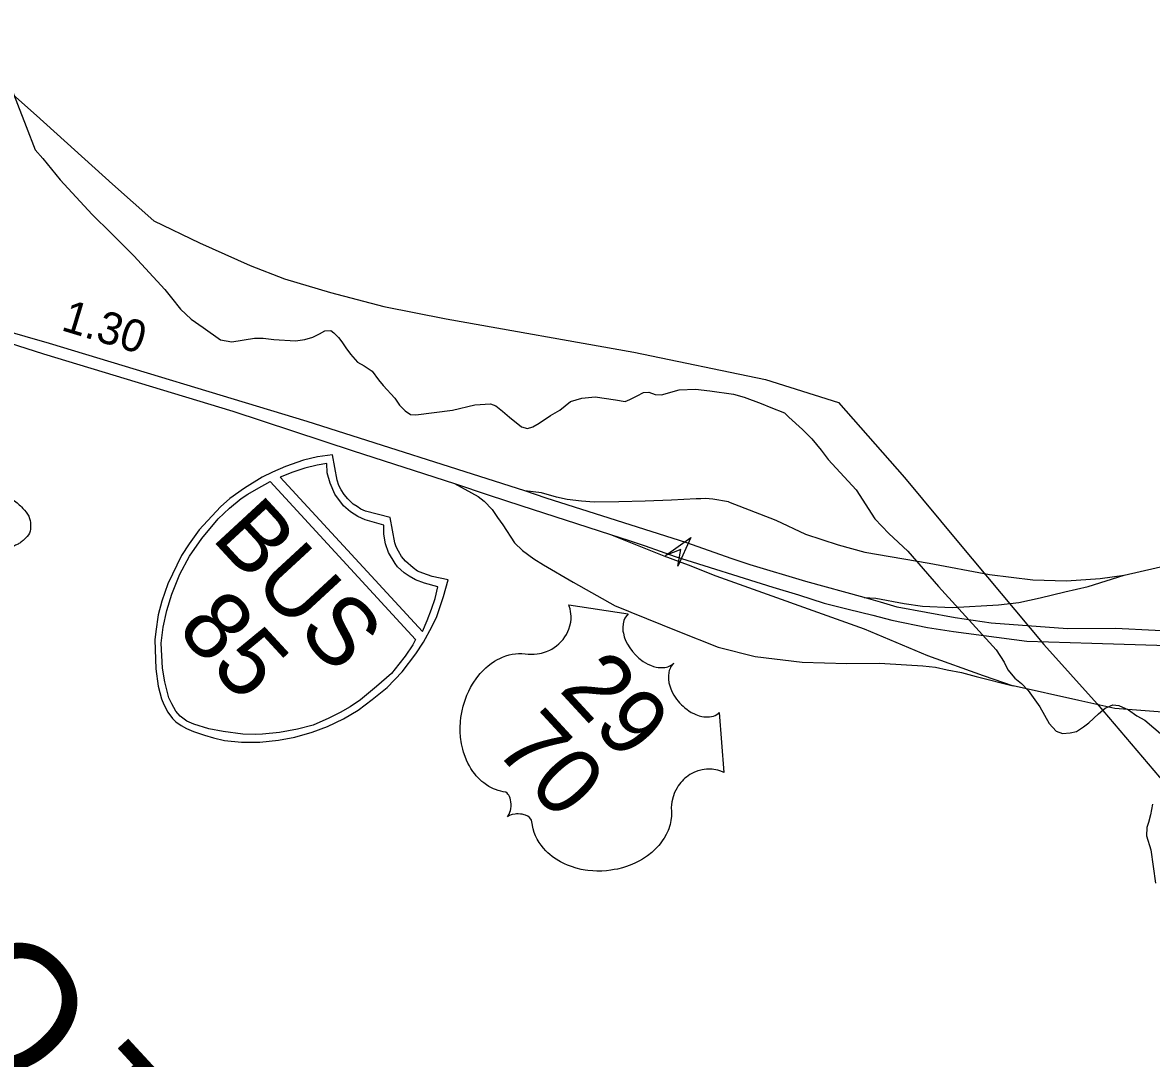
# Model space of a CAD drawing. Extents: x 1695041 to 1706254, y 786537 to 798223.
# Drawn here: x 1703431.2 to 1703634.1, y 796781.2 to 796967.3 of the extents above; entities that cross this region are included whole.
import ezdxf

# ---------------------------------------------------------------- set-up
doc = ezdxf.new("R2010")
doc.units = 0
for name, color, linetype in [('Default', 7, 'Continuous'), ('Old_Level_2', 7, 'Continuous'), ('Old_Level_27', 7, 'Continuous'), ('Old_Level_30', 7, 'Continuous'), ('Old_Level_47', 7, 'Continuous')]:
    doc.layers.add(name, color=color, linetype=linetype)

msp = doc.modelspace()

# ---------------------------------------------------------------- linework, layer by layer
at = {"layer": 'Default'}
msp.add_lwpolyline([(1703414.85, 796967.32), (1703433.69, 796950.61), (1703447.36, 796938.29), (1703454.79, 796931.67), (1703463.03, 796927.76), (1703472.14, 796923.67), (1703478.29, 796921.24), (1703486.59, 796918.81), (1703496.14, 796916.29), (1703507.34, 796914.06), (1703541.09, 796908.09), (1703564.75, 796903.15), (1703577.89, 796899.03), (1703589.73, 796885.57), (1703599.49, 796873.87), (1703614.79, 796855.58), (1703624.36, 796844.92), (1703635.61, 796831.69), (1703649.41, 796815.64), (1703662.09, 796801.81), (1703669.34, 796799.45)], dxfattribs=at)
for points in [[(1703458.16, 796842.23), (1703458.78, 796841.67), (1703459.69, 796841), (1703460.68, 796840.45), (1703461.92, 796839.91), (1703463.9, 796839.26), (1703465.52, 796838.77), (1703467.5, 796838.29), (1703470.57, 796838.02), (1703473.87, 796837.98), (1703477.23, 796838.34), (1703480.17, 796838.89), (1703483.25, 796839.82), (1703486.03, 796840.79), (1703488.93, 796842.19), (1703491.54, 796843.77), (1703494.05, 796845.66), (1703496.73, 796847.85), (1703499.43, 796850.66), (1703501.89, 796853.86), (1703503.28, 796856), (1703504.81, 796858.72), (1703505.66, 796860.58), (1703506.9, 796864.2), (1703507.69, 796867.15), (1703504.84, 796867.77), (1703503.18, 796868.35), (1703502.23, 796868.75), (1703501.43, 796869.34), (1703500.05, 796870.51), (1703499.33, 796871.37), (1703498.79, 796872.3), (1703498.34, 796873.08), (1703498.11, 796873.85), (1703497.32, 796878.38), (1703492.86, 796879.53), (1703492.04, 796879.87), (1703491.35, 796880.36), (1703490.64, 796880.8), (1703489.7, 796881.73), (1703489.04, 796882.49), (1703488.47, 796883.38), (1703488.04, 796884.1), (1703487.74, 796885.07), (1703486.91, 796889.66), (1703484.21, 796889.28), (1703481.72, 796888.7), (1703478.5, 796887.56), (1703476.15, 796886.52), (1703474.28, 796885.6), (1703471.09, 796883.65), (1703468.49, 796881.77), (1703466.79, 796880.28), (1703462.93, 796876.16), (1703461.14, 796873.67), (1703459.78, 796871.56), (1703457.35, 796866.47), (1703456.25, 796863.33), (1703455.61, 796860.91), (1703455.15, 796857.91), (1703455.01, 796856.39), (1703455.15, 796851.2), (1703455.61, 796848.07), (1703456.2, 796845.77), (1703456.59, 796844.79), (1703457.32, 796843.37)], [(1703485.89, 796888.09), (1703484.16, 796887.79), (1703481.94, 796887.25), (1703479.82, 796886.5), (1703477.53, 796885.62), (1703503.08, 796857.91), (1703503.93, 796859.88), (1703504.74, 796861.91), (1703505.39, 796863.85), (1703505.86, 796865.91), (1703503.44, 796866.56), (1703501.86, 796867.19), (1703500.71, 796867.82), (1703499.83, 796868.43), (1703498.63, 796869.53), (1703498.17, 796870.09), (1703497.01, 796872.11), (1703496.43, 796873.66), (1703496.16, 796875.39), (1703496.17, 796877.01), (1703492.82, 796877.98), (1703491.49, 796878.56), (1703490.17, 796879.41), (1703488.89, 796880.5), (1703487.35, 796882.58), (1703486.49, 796884.53), (1703485.98, 796886.42)], [(1703501.87, 796856.48), (1703501.36, 796855.47), (1703500, 796853.45), (1703498.86, 796852.01), (1703497.53, 796850.36), (1703494.81, 796848), (1703491.96, 796845.61), (1703490.11, 796844.37), (1703488.33, 796843.34), (1703486.27, 796842.29), (1703483.42, 796841.03), (1703480.64, 796840.35), (1703477.42, 796839.74), (1703474.36, 796839.47), (1703473.06, 796839.39), (1703470.81, 796839.42), (1703467.24, 796839.95), (1703464.72, 796840.42), (1703461.99, 796841.24), (1703460.73, 796841.78), (1703459.52, 796842.65), (1703458.77, 796843.58), (1703458.07, 796844.91), (1703457.51, 796845.99), (1703456.78, 796848.82), (1703456.39, 796851.3), (1703456.13, 796855.78), (1703456.47, 796858.65), (1703457.17, 796861.68), (1703458.04, 796864.61), (1703459.46, 796868.18), (1703461.22, 796871.41), (1703463.41, 796874.59), (1703466.39, 796878.13), (1703468.41, 796880.08), (1703470.5, 796881.78), (1703471.72, 796882.55), (1703473.24, 796883.49), (1703475.69, 796884.82)], [(1703546.78, 796871.52), (1703551.36, 796874.79), (1703549.03, 796869.66), (1703549.57, 796872.62)], [(1703540.06, 796861.05), (1703539.82, 796860.79), (1703539.57, 796860.45), (1703539.46, 796860.26), (1703539.29, 796859.84), (1703539.15, 796859.27), (1703539.11, 796858.63), (1703539.14, 796857.98), (1703539.21, 796857.58), (1703539.38, 796856.94), (1703539.62, 796856.28), (1703539.96, 796855.6), (1703540.35, 796854.95), (1703540.84, 796854.3), (1703541.37, 796853.7), (1703542.01, 796853.1), (1703542.79, 796852.53), (1703543.18, 796852.28), (1703543.63, 796852.03), (1703544.08, 796851.82), (1703544.62, 796851.63), (1703545.09, 796851.51), (1703545.47, 796851.44), (1703546.09, 796851.4), (1703546.66, 796851.44), (1703546.94, 796851.5), (1703547.21, 796851.56), (1703547.7, 796851.78), (1703547.9, 796851.89), (1703548.27, 796852.18), (1703548, 796851.9), (1703547.85, 796851.7), (1703547.71, 796851.49), (1703547.6, 796851.25), (1703547.45, 796850.87), (1703547.37, 796850.52), (1703547.3, 796849.94), (1703547.3, 796849.62), (1703547.31, 796849.35), (1703547.41, 796848.66), (1703547.62, 796847.94), (1703547.73, 796847.6), (1703547.88, 796847.27), (1703548.07, 796846.86), (1703548.3, 796846.47), (1703548.54, 796846.09), (1703548.79, 796845.72), (1703549.08, 796845.36), (1703549.33, 796845.08), (1703549.64, 796844.74), (1703549.95, 796844.45), (1703550.28, 796844.17), (1703550.66, 796843.87), (1703550.98, 796843.64), (1703551.43, 796843.36), (1703551.86, 796843.14), (1703552.26, 796842.96), (1703552.82, 796842.76), (1703553.3, 796842.63), (1703553.69, 796842.57), (1703554.19, 796842.53), (1703554.72, 796842.55), (1703555.08, 796842.59), (1703555.4, 796842.69), (1703555.73, 796842.81), (1703556.03, 796842.98), (1703556.27, 796843.15), (1703556.46, 796843.32), (1703557.25, 796832.56), (1703557.06, 796832.65), (1703556.58, 796832.83), (1703556.18, 796832.96), (1703555.48, 796833.11), (1703555.15, 796833.14), (1703554.81, 796833.16), (1703554.47, 796833.16), (1703554.16, 796833.15), (1703553.75, 796833.1), (1703553.35, 796833.03), (1703552.93, 796832.93), (1703552.58, 796832.83), (1703551.91, 796832.56), (1703551.51, 796832.36), (1703551.19, 796832.17), (1703550.57, 796831.74), (1703550.29, 796831.51), (1703550.03, 796831.27), (1703549.76, 796831), (1703549.52, 796830.73), (1703549.29, 796830.43), (1703549.09, 796830.16), (1703548.87, 796829.81), (1703548.62, 796829.39), (1703548.42, 796828.94), (1703548.14, 796828.16), (1703547.93, 796827.29), (1703547.86, 796826.75), (1703547.83, 796826.25), (1703547.86, 796825.56), (1703547.87, 796825.19), (1703547.85, 796824.73), (1703547.76, 796823.93), (1703547.69, 796823.57), (1703547.6, 796823.19), (1703547.49, 796822.82), (1703547.36, 796822.43), (1703547.24, 796822.1), (1703546.91, 796821.39), (1703546.54, 796820.76), (1703546.33, 796820.43), (1703545.83, 796819.76), (1703545.57, 796819.43), (1703545.02, 796818.84), (1703544.31, 796818.17), (1703543.57, 796817.6), (1703542.66, 796816.99), (1703542.09, 796816.66), (1703541.38, 796816.31), (1703540.76, 796816.03), (1703539.79, 796815.66), (1703539.04, 796815.44), (1703538.14, 796815.21), (1703537.57, 796815.1), (1703536.94, 796815), (1703536.2, 796814.91), (1703535.37, 796814.85), (1703534.44, 796814.85), (1703533.73, 796814.87), (1703532.85, 796814.96), (1703532.34, 796815.03), (1703531.64, 796815.15), (1703530.73, 796815.37), (1703529.89, 796815.64), (1703529.2, 796815.89), (1703528.62, 796816.15), (1703527.91, 796816.5), (1703526.81, 796817.18), (1703526.43, 796817.45), (1703526.01, 796817.79), (1703525.63, 796818.13), (1703525.28, 796818.47), (1703524.83, 796818.95), (1703524.42, 796819.47), (1703524.07, 796819.98), (1703523.73, 796820.55), (1703523.42, 796821.18), (1703523.19, 796821.79), (1703522.99, 796822.45), (1703522.77, 796823.66), (1703522.68, 796823.99), (1703522.6, 796824.15), (1703522.34, 796824.46), (1703522.02, 796824.68), (1703521.64, 796824.86), (1703521.39, 796824.95), (1703521.03, 796825.04), (1703520.73, 796825.09), (1703520.33, 796825.11), (1703520.03, 796825.1), (1703519.79, 796825.09), (1703519.25, 796824.99), (1703519.02, 796824.92), (1703518.74, 796824.81), (1703518.37, 796824.6), (1703518.66, 796825.05), (1703518.82, 796825.4), (1703518.91, 796825.74), (1703518.98, 796826.05), (1703519.03, 796826.5), (1703519.04, 796826.87), (1703519.01, 796827.28), (1703518.93, 796827.67), (1703518.85, 796827.96), (1703518.75, 796828.21), (1703518.6, 796828.48), (1703518.45, 796828.68), (1703518.3, 796828.82), (1703518.07, 796828.99), (1703517.61, 796829.08), (1703517.18, 796829.18), (1703516.73, 796829.3), (1703516.23, 796829.48), (1703515.88, 796829.62), (1703515.48, 796829.81), (1703515.04, 796830.06), (1703514.59, 796830.35), (1703514.15, 796830.67), (1703513.78, 796830.96), (1703513.41, 796831.3), (1703513.09, 796831.62), (1703512.77, 796831.97), (1703512.49, 796832.32), (1703512.18, 796832.73), (1703511.82, 796833.26), (1703511.55, 796833.73), (1703511.28, 796834.25), (1703511.02, 796834.79), (1703510.78, 796835.4), (1703510.5, 796836.19), (1703510.34, 796836.77), (1703510.13, 796837.71), (1703509.96, 796838.9), (1703509.9, 796839.86), (1703509.89, 796840.59), (1703509.95, 796841.74), (1703510.02, 796842.45), (1703510.22, 796843.64), (1703510.41, 796844.46), (1703510.57, 796845.03), (1703510.87, 796845.91), (1703511.08, 796846.44), (1703511.41, 796847.18), (1703511.75, 796847.83), (1703512.08, 796848.43), (1703512.31, 796848.79), (1703512.73, 796849.4), (1703513.04, 796849.82), (1703513.49, 796850.36), (1703514.01, 796850.91), (1703514.5, 796851.38), (1703514.93, 796851.75), (1703515.46, 796852.15), (1703516.05, 796852.55), (1703516.59, 796852.86), (1703516.99, 796853.06), (1703517.5, 796853.29), (1703518.09, 796853.51), (1703518.69, 796853.68), (1703519.21, 796853.8), (1703519.8, 796853.89), (1703520.34, 796853.94), (1703520.98, 796853.94), (1703521.59, 796853.9), (1703522.12, 796853.83), (1703522.8, 796853.79), (1703523.19, 796853.8), (1703523.69, 796853.85), (1703524.13, 796853.92), (1703524.51, 796854.01), (1703525.05, 796854.15), (1703525.42, 796854.29), (1703525.97, 796854.53), (1703526.33, 796854.73), (1703526.78, 796855.01), (1703527.18, 796855.29), (1703527.64, 796855.68), (1703527.99, 796856.03), (1703528.38, 796856.47), (1703528.71, 796856.93), (1703528.98, 796857.36), (1703529.25, 796857.89), (1703529.42, 796858.31), (1703529.61, 796858.93), (1703529.74, 796859.54), (1703529.8, 796860.09), (1703529.82, 796860.62), (1703529.78, 796861.08), (1703529.73, 796861.49), (1703529.63, 796861.98), (1703529.5, 796862.43), (1703529.4, 796862.69)]]:
    msp.add_lwpolyline(points, close=True, dxfattribs=at)
msp.add_open_spline([(1703427.95, 796882.37), (1703428.62, 796882.11), (1703429.54, 796881.5), (1703430.47, 796880.88), (1703431.15, 796880.14), (1703432.56, 796878.61), (1703432.63, 796877.07), (1703432.69, 796875.52), (1703431.43, 796874.36), (1703430.87, 796873.83), (1703430.25, 796873.53), (1703429.62, 796873.22), (1703428.92, 796873.09), (1703428.27, 796872.97), (1703427.55, 796872.95), (1703426.83, 796872.93), (1703425.88, 796872.98), (1703424.52, 796873.05), (1703423.16, 796873.21), (1703421.8, 796873.36), (1703420.63, 796873.51)], degree=3, dxfattribs=at)
at = {"layer": 'Old_Level_27'}
for points in [[(1703405.06, 796916.66), (1703416.6, 796913.66), (1703434.95, 796907.77), (1703469.02, 796897.48), (1703490.65, 796890.37), (1703508.83, 796884.48)], [(1703521.5, 796883.15), (1703482.35, 796895.62), (1703436.05, 796909.65), (1703422.42, 796913.54), (1703409.3, 796917.03)], [(1703508.83, 796884.48), (1703515.1, 796882.38), (1703520.76, 796880.56), (1703536.91, 796875.33)], [(1703550.62, 796873.81), (1703525.31, 796881.85), (1703521.5, 796883.15)], [(1703536.91, 796875.33), (1703540.28, 796874.25), (1703543.15, 796873.28), (1703548.53, 796871.37)], [(1703582.51, 796864), (1703572.01, 796866.87), (1703562.02, 796869.86), (1703558.61, 796871), (1703550.62, 796873.81)], [(1703548.53, 796871.37), (1703566.06, 796865.83), (1703570.71, 796864.5), (1703575.31, 796863), (1703579.65, 796861.89), (1703584.08, 796860.85), (1703587.47, 796859.94), (1703593.9, 796858.6), (1703598.58, 796857.87), (1703611.75, 796856.13), (1703623.45, 796855.82), (1703640.92, 796855.28), (1703649.76, 796855.1)], [(1703650.31, 796857.69), (1703641.96, 796857.69), (1703627.68, 796858.45), (1703619.04, 796858.36), (1703605.35, 796859.39), (1703598.85, 796860.35), (1703588.44, 796862.27), (1703585.42, 796863.18), (1703582.51, 796864)]]:
    msp.add_lwpolyline(points, dxfattribs=at)
at = {"layer": 'Old_Level_30'}
for points in [[(1703428.73, 796956.65), (1703431.83, 796948.66), (1703433.5, 796944.46), (1703434.85, 796942.89), (1703437.97, 796939.06), (1703443.74, 796932.82), (1703447.12, 796929.5), (1703451.2, 796925.41), (1703456.78, 796919.36), (1703457.99, 796917.87), (1703459.62, 796915.84), (1703461.49, 796914.01), (1703463.66, 796912.5), (1703466.81, 796910.28), (1703468.83, 796909.92), (1703472.91, 796910.58), (1703474.48, 796910.58), (1703476.36, 796910.34), (1703480.3, 796910.13), (1703481.95, 796910.35), (1703483.38, 796910.76), (1703484.57, 796911.41), (1703485.57, 796911.9), (1703486.6, 796912), (1703487.16, 796911.55), (1703487.99, 796910.71), (1703488.59, 796909.95), (1703489.31, 796908.84), (1703490.19, 796907.73), (1703491.41, 796906.3), (1703492.6, 796905.64), (1703494.08, 796904.68), (1703495.21, 796903.13), (1703496.03, 796902.12), (1703498.12, 796899.84), (1703498.95, 796898.55), (1703500.01, 796897.53), (1703500.94, 796896.87), (1703501.9, 796896.82), (1703508.48, 796897.69), (1703512.52, 796898.61), (1703515.3, 796898.8), (1703516.29, 796898.45), (1703517.46, 796897.51), (1703518.73, 796896.39), (1703520.91, 796894.66), (1703521.96, 796894.39), (1703522.92, 796894.69), (1703524.07, 796895.31), (1703526.1, 796896.71), (1703527.78, 796897.64), (1703529.68, 796899.21), (1703531.76, 796899.83), (1703534.14, 796900.04), (1703537.82, 796899.54), (1703539.55, 796899.22), (1703540.4, 796899.58)], [(1703540.4, 796899.58), (1703541.7, 796900.25), (1703542.84, 796900.82), (1703543.78, 796900.9), (1703544.94, 796900.47), (1703546.04, 796900.45), (1703549.23, 796901.3), (1703552.18, 796901.45), (1703554.74, 796901.17), (1703558.99, 796900.55), (1703560.91, 796899.98), (1703563.99, 796898.86), (1703565.71, 796898.16), (1703568.2, 796897.16), (1703568.95, 796896.4), (1703571.39, 796894.18), (1703573.11, 796892.52), (1703574.8, 796890.49), (1703576.02, 796888.78), (1703581.06, 796883.38), (1703584.42, 796878.15), (1703586.95, 796875.49), (1703590.33, 796872.32), (1703593.09, 796869.14), (1703595.87, 796865.99), (1703606.23, 796854.62), (1703607.66, 796852.41), (1703608.31, 796850.99), (1703609.6, 796849.48), (1703610.81, 796848.55), (1703612.01, 796847.3), (1703614.1, 796844.37), (1703615.79, 796841.37), (1703617.04, 796839.99), (1703618.18, 796839.59), (1703619.53, 796839.7), (1703620.69, 796839.93), (1703621.94, 796840.74), (1703622.88, 796841.5), (1703624.62, 796843.12), (1703625.81, 796844.11), (1703627.18, 796844.73), (1703628.3, 796844.57), (1703630.02, 796843.8), (1703631.53, 796842.75), (1703632.96, 796841.93), (1703636.22, 796839.2)], [(1703634.34, 796826.84), (1703633.96, 796824.93), (1703633.62, 796823.58), (1703633.29, 796822.64), (1703633.28, 796821.18), (1703634.04, 796818.65), (1703634.9, 796812.64)]]:
    msp.add_lwpolyline(points, dxfattribs=at)
at = {"layer": 'Old_Level_47'}
for points in [[(1703508.83, 796884.48), (1703513.13, 796882.14), (1703514.17, 796881.29), (1703515.63, 796879.83), (1703516.61, 796878.38), (1703517.56, 796877.06), (1703519.65, 796873.82), (1703521.07, 796872.42), (1703523.09, 796870.93), (1703524.86, 796869.85), (1703530.18, 796866.75), (1703537.73, 796862.49), (1703539.72, 796861.74), (1703540.58, 796861.37)], [(1703558.09, 796881.17), (1703555.31, 796881.65), (1703554, 796881.78), (1703553.15, 796881.76), (1703552.28, 796881.73), (1703547.84, 796881.5), (1703543.13, 796881.29), (1703538.42, 796881.2), (1703533.98, 796881.11), (1703531.71, 796881.34), (1703529.1, 796881.64), (1703527.17, 796882.05), (1703524.51, 796882.83), (1703521.5, 796883.15)], [(1703558.09, 796881.17), (1703566.6, 796877.89), (1703571.94, 796875.38), (1703577.84, 796873.46), (1703582.61, 796872.17), (1703594.21, 796870.18), (1703605.04, 796868.13), (1703612.85, 796867.17), (1703618.9, 796866.98), (1703624.91, 796867.41), (1703629.24, 796868)], [(1703536.91, 796875.33), (1703546.48, 796871.47), (1703550.87, 796869.85), (1703555.84, 796867.87), (1703582.48, 796858.38), (1703593.86, 796853.57), (1703603.91, 796849.98), (1703609.29, 796848.12)], [(1703629.24, 796868), (1703637.87, 796870.01), (1703639.56, 796870.31), (1703642.43, 796870.76), (1703645.58, 796870.92), (1703648.85, 796870.95), (1703653.4, 796870.82)], [(1703582.51, 796864), (1703584.59, 796863.88), (1703589.68, 796862.95), (1703593, 796862.46), (1703598.32, 796862.21), (1703606.64, 796862.7), (1703610.29, 796863.11), (1703614.14, 796863.97), (1703618.57, 796865), (1703622.8, 796865.97), (1703629.24, 796868)], [(1703540.58, 796861.37), (1703548.99, 796857.95), (1703556.23, 796855.07), (1703562.93, 796853.41), (1703571.34, 796852.37), (1703579.38, 796852.15), (1703585.25, 796852.21), (1703590.11, 796851.91), (1703593.02, 796851.71), (1703595.3, 796851.49), (1703597.41, 796850.98), (1703600, 796850.55), (1703602.62, 796849.82), (1703609.29, 796848.12)], [(1703647.04, 796842.54), (1703627.54, 796844.07), (1703621.08, 796845.48), (1703609.29, 796848.12)]]:
    msp.add_lwpolyline(points, dxfattribs=at)

# ---------------------------------------------------------------- texts
at = {"layer": 'Default'}
for s, height, rotation, p in [('1.30', 5.775, 343.1351, (1703437.95, 796912.09)), ('BUS', 12.229, 312.7091, (1703464.99, 796874.62)), ('85', 12.229, 312.7091, (1703458.65, 796858.14)), ('29', 12.01, 312.7091, (1703527.48, 796847.35)), ('70', 12.01, 312.7091, (1703515.79, 796836.73))]:
    msp.add_text(s, height=height, rotation=rotation, dxfattribs=at).set_placement(p)
at = {"layer": 'Old_Level_2'}
for s, height, p in [('PROJECT ', 23.173, (1703383.41, 796822.91)), ('SITE', 27.263, (1703367.32, 796777.31))]:
    msp.add_text(s, height=height, rotation=312.7091, dxfattribs=at).set_placement(p)

doc.saveas('drawing.dxf')
